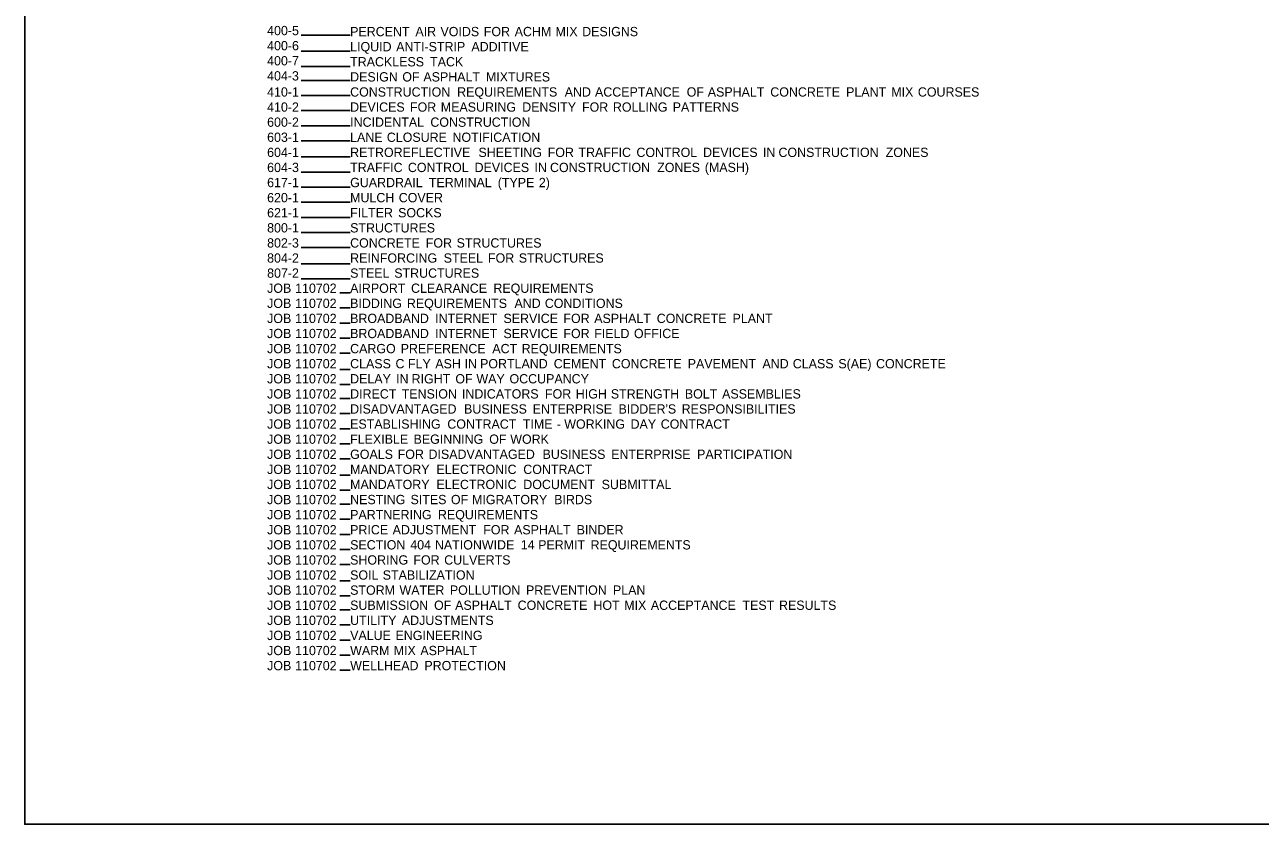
# Model space of a CAD drawing. Extents: x 1955683 to 1956002, y 566394 to 566602.
# Drawn here: x 1955683.4 to 1955842.9, y 566393.5 to 566496.8 of the extents above; entities that cross this region are included whole.
import ezdxf

# ---------------------------------------------------------------- set-up
doc = ezdxf.new("R2010")
doc.units = 0
doc.layers.add('Default', color=7, linetype='Continuous')
doc.layers.add('R_Border Prem', color=7, linetype='Continuous')

msp = doc.modelspace()

# ---------------------------------------------------------------- linework, layer by layer
at = {"layer": 'Default'}
for p, q in [((1955719.09, 566495.45), (1955725.4, 566495.45)), ((1955719.09, 566493.36), (1955725.4, 566493.36)), ((1955719.09, 566491.41), (1955725.4, 566491.41)), ((1955719.09, 566489.6), (1955725.4, 566489.6)), ((1955719.09, 566487.65), (1955725.4, 566487.65)), ((1955719.09, 566485.7), (1955725.4, 566485.7)), ((1955719.09, 566483.75), (1955725.4, 566483.75)), ((1955719.09, 566481.8), (1955725.4, 566481.8)), ((1955719.09, 566479.71), (1955725.4, 566479.71)), ((1955719.09, 566477.76), (1955725.4, 566477.76)), ((1955719.09, 566475.81), (1955725.4, 566475.81)), ((1955719.09, 566473.86), (1955725.4, 566473.86)), ((1955719.09, 566471.91), (1955725.4, 566471.91)), ((1955719.09, 566469.96), (1955725.4, 566469.96)), ((1955719.09, 566468.01), (1955725.4, 566468.01)), ((1955719.09, 566465.92), (1955725.4, 566465.92)), ((1955719.09, 566463.97), (1955725.4, 566463.97)), ((1955724.06, 566462.16), (1955725.4, 566462.16)), ((1955724.06, 566460.21), (1955725.4, 566460.21)), ((1955724.06, 566458.26), (1955725.4, 566458.26)), ((1955724.06, 566456.31), (1955725.4, 566456.31)), ((1955724.06, 566454.36), (1955725.4, 566454.36)), ((1955724.06, 566452.27), (1955725.4, 566452.27)), ((1955724.06, 566450.32), (1955725.4, 566450.32)), ((1955724.06, 566448.51), (1955725.4, 566448.51)), ((1955724.06, 566446.56), (1955725.4, 566446.56)), ((1955724.06, 566444.61), (1955725.4, 566444.61)), ((1955724.06, 566442.66), (1955725.4, 566442.66)), ((1955724.06, 566440.71), (1955725.4, 566440.71)), ((1955724.06, 566438.62), (1955725.4, 566438.62)), ((1955724.06, 566436.67), (1955725.4, 566436.67)), ((1955724.06, 566434.86), (1955725.4, 566434.86)), ((1955724.06, 566432.91), (1955725.4, 566432.91)), ((1955724.06, 566430.96), (1955725.4, 566430.96)), ((1955724.06, 566429.01), (1955725.4, 566429.01)), ((1955724.06, 566427.06), (1955725.4, 566427.06)), ((1955724.06, 566424.97), (1955725.4, 566424.97)), ((1955724.06, 566423.02), (1955725.4, 566423.02)), ((1955724.06, 566421.21), (1955725.4, 566421.21)), ((1955724.06, 566419.26), (1955725.4, 566419.26)), ((1955724.06, 566417.31), (1955725.4, 566417.31)), ((1955724.06, 566415.36), (1955725.4, 566415.36)), ((1955724.06, 566413.41), (1955725.4, 566413.41))]:
    msp.add_line(p, q, dxfattribs=at)
at = {"layer": 'R_Border Prem'}
msp.add_lwpolyline([(1956002.45, 566561.79), (1956002.45, 566393.51), (1955683.38, 566393.51), (1955683.38, 566601.97), (1955920.19, 566601.97), (1955920.19, 566592.09), (1955955.71, 566592.09), (1955955.71, 566588.52), (1955959.35, 566588.52), (1955959.35, 566589.17), (1955974.89, 566589.17)], dxfattribs=at)

# ---------------------------------------------------------------- texts
at = {"layer": 'Default'}
for s, p in [('400-5', (1955714.68, 566495.44)), ('PERCENT', (1955725.4, 566495.31)), (' AIR', (1955733.38, 566495.31)), (' VOIDS', (1955736.62, 566495.31)), (' FOR', (1955742.21, 566495.31)), (' ACHM', (1955746.2, 566495.31)), (' MIX', (1955751.47, 566495.31)), (' DESIGNS', (1955754.91, 566495.31)), ('400-6', (1955714.68, 566493.49)), ('LIQUID', (1955725.4, 566493.36)), (' ANTI-STRIP', (1955730.9, 566493.36)), (' ADDITIVE', (1955740.61, 566493.36)), ('400-7', (1955714.68, 566491.54)), ('TRACKLESS', (1955725.4, 566491.41)), (' TACK', (1955735.28, 566491.41)), ('404-3', (1955714.68, 566489.59)), ('DESIGN', (1955725.4, 566489.46)), (' OF', (1955731.69, 566489.46)), (' ASPHALT', (1955734.41, 566489.46)), (' MIXTURES', (1955742.48, 566489.46)), ('410-1', (1955714.68, 566487.51)), ('CONSTRUCTION', (1955725.4, 566487.51)), (' REQUIREMENTS', (1955738.77, 566487.51)), (' AND', (1955752.66, 566487.51)), (' ACCEPTANCE', (1955756.57, 566487.51)), (' OF', (1955768.41, 566487.51)), (' ASPHALT', (1955771.13, 566487.51)), (' CONCRETE', (1955779.2, 566487.51)), (' PLANT', (1955788.99, 566487.51)), (' MIX', (1955794.82, 566487.51)), (' COURSES', (1955798.26, 566487.51)), ('410-2', (1955714.68, 566485.56)), ('DEVICES', (1955725.4, 566485.56)), (' FOR', (1955732.68, 566485.56)), (' MEASURING', (1955736.66, 566485.56)), (' DENSITY', (1955747.17, 566485.56)), (' FOR', (1955754.89, 566485.56)), (' ROLLING', (1955758.88, 566485.56)), (' PATTERNS', (1955766.6, 566485.56)), ('600-2', (1955714.68, 566483.61)), ('INCIDENTAL', (1955725.4, 566483.61)), (' CONSTRUCTION', (1955735.31, 566483.61)), ('603-1', (1955714.68, 566481.66)), ('LANE', (1955725.4, 566481.66)), (' CLOSURE', (1955729.69, 566481.66)), (' NOTIFICATION', (1955738.17, 566481.66)), ('604-1', (1955714.68, 566479.71)), ('RETROREFLECTIVE', (1955725.4, 566479.71)), (' SHEETING', (1955741.52, 566479.71)), (' FOR', (1955750.46, 566479.71)), (' TRAFFIC', (1955754.44, 566479.71)), (' CONTROL', (1955761.92, 566479.71)), (' DEVICES', (1955770.52, 566479.71)), (' IN', (1955778.26, 566479.71)), (' CONSTRUCTION', (1955780.26, 566479.71)), (' ZONES', (1955794.1, 566479.71)), ('604-3', (1955714.68, 566477.76)), ('TRAFFIC', (1955725.4, 566477.76)), (' CONTROL', (1955732.41, 566477.76)), (' DEVICES', (1955741.02, 566477.76)), (' IN', (1955748.76, 566477.76)), (' CONSTRUCTION', (1955750.76, 566477.76)), (' ZONES', (1955764.6, 566477.76)), (' (MASH)', (1955770.75, 566477.76)), ('617-1', (1955714.68, 566475.81)), ('GUARDRAIL', (1955725.4, 566475.81)), (' TERMINAL', (1955735.12, 566475.81)), (' (TYPE', (1955744.01, 566475.81)), (' 2)', (1955749.32, 566475.81)), ('620-1', (1955714.68, 566473.86)), ('MULCH', (1955725.4, 566473.86)), (' COVER', (1955731.23, 566473.86)), ('621-1', (1955714.68, 566471.91)), ('FILTER', (1955725.4, 566471.91)), (' SOCKS', (1955731.15, 566471.91)), ('800-1', (1955714.68, 566469.96)), ('STRUCTURES', (1955725.4, 566469.96)), ('802-3', (1955714.68, 566468.01)), ('CONCRETE', (1955725.4, 566468.01)), (' FOR', (1955734.72, 566468.01)), (' STRUCTURES', (1955738.7, 566468.01)), ('804-2', (1955714.68, 566466.06)), ('REINFORCING', (1955725.4, 566466.06)), (' STEEL', (1955737.03, 566466.06)), (' FOR', (1955742.75, 566466.06)), (' STRUCTURES', (1955746.73, 566466.06)), ('807-2', (1955714.68, 566464.11)), ('STEEL', (1955725.4, 566464.11)), (' STRUCTURES', (1955730.65, 566464.11)), ('JOB', (1955714.68, 566462.16)), (' 110702', (1955717.85, 566462.16)), ('AIRPORT', (1955725.4, 566462.16)), (' CLEARANCE', (1955732.82, 566462.16)), (' REQUIREMENTS', (1955743.45, 566462.16)), ('JOB', (1955714.68, 566460.21)), (' 110702', (1955717.85, 566460.21)), ('BIDDING', (1955725.4, 566460.21)), (' REQUIREMENTS', (1955732.28, 566460.21)), (' AND', (1955746.17, 566460.21)), (' CONDITIONS', (1955750.09, 566460.21)), ('JOB', (1955714.68, 566458.26)), (' 110702', (1955717.85, 566458.26)), ('BROADBAND', (1955725.4, 566458.26)), (' INTERNET', (1955735.93, 566458.26)), (' SERVICE', (1955744.75, 566458.26)), (' FOR', (1955752.49, 566458.26)), (' ASPHALT', (1955756.47, 566458.26)), (' CONCRETE', (1955764.54, 566458.26)), (' PLANT', (1955774.33, 566458.26)), ('JOB', (1955714.68, 566456.31)), (' 110702', (1955717.85, 566456.31)), ('BROADBAND', (1955725.4, 566456.31)), (' INTERNET', (1955735.93, 566456.31)), (' SERVICE', (1955744.75, 566456.31)), (' FOR', (1955752.49, 566456.31)), (' FIELD', (1955756.47, 566456.31)), (' OFFICE', (1955761.6, 566456.31)), ('JOB', (1955714.68, 566454.36)), (' 110702', (1955717.85, 566454.36)), ('CARGO', (1955725.4, 566454.36)), (' PREFERENCE', (1955731.48, 566454.36)), (' ACT', (1955743.31, 566454.36)), (' REQUIREMENTS', (1955747.1, 566454.36)), ('JOB', (1955714.68, 566452.41)), (' 110702', (1955717.85, 566452.41)), ('CLASS', (1955725.4, 566452.41)), (' C', (1955730.81, 566452.41)), (' FLY', (1955732.42, 566452.41)), (' ASH', (1955735.95, 566452.41)), (' IN', (1955739.73, 566452.41)), (' PORTLAND', (1955741.73, 566452.41)), (' CEMENT', (1955751.24, 566452.41)), (' CONCRETE', (1955758.75, 566452.41)), (' PAVEMENT', (1955768.54, 566452.41)), (' AND', (1955778.19, 566452.41)), (' CLASS', (1955782.11, 566452.41)), (' S(AE)', (1955787.99, 566452.41)), (' CONCRETE', (1955792.86, 566452.41)), ('JOB', (1955714.68, 566450.46)), (' 110702', (1955717.85, 566450.46)), ('DELAY', (1955725.4, 566450.46)), (' IN', (1955730.89, 566450.46)), (' RIGHT', (1955732.89, 566450.46)), (' OF', (1955738.54, 566450.46)), (' WAY', (1955741.26, 566450.46)), (' OCCUPANCY', (1955745.53, 566450.46)), ('JOB', (1955714.68, 566448.51)), (' 110702', (1955717.85, 566448.51)), ('DIRECT', (1955725.4, 566448.51)), (' TENSION', (1955731.61, 566448.51)), (' INDICATORS', (1955739.39, 566448.51)), (' FOR', (1955750.11, 566448.51)), (' HIGH', (1955754.09, 566448.51)), (' STRENGTH', (1955758.61, 566448.51)), (' BOLT', (1955768.17, 566448.51)), (' ASSEMBLIES', (1955772.98, 566448.51)), ('JOB', (1955714.68, 566446.56)), (' 110702', (1955717.85, 566446.56)), ('DISADVANTAGED', (1955725.4, 566446.56)), (' BUSINESS', (1955739.66, 566446.56)), (' ENTERPRISE', (1955748.52, 566446.56)), (" BIDDER'S", (1955759.61, 566446.56)), (' RESPONSIBILITIES', (1955767.76, 566446.56)), ('JOB', (1955714.68, 566444.61)), (' 110702', (1955717.85, 566444.61)), ('ESTABLISHING', (1955725.4, 566444.61)), (' CONTRACT', (1955737.5, 566444.61)), (' TIME', (1955747.25, 566444.61)), (' WORKING', (1955752.6, 566444.61)), (' DAY', (1955761.16, 566444.61)), (' CONTRACT', (1955765.06, 566444.61)), (' -', (1955751.63, 566444.61)), ('JOB', (1955714.68, 566442.66)), (' 110702', (1955717.85, 566442.66)), ('FLEXIBLE', (1955725.4, 566442.66)), (' BEGINNING', (1955733.14, 566442.66)), (' OF', (1955742.91, 566442.66)), (' WORK', (1955745.63, 566442.66)), ('JOB', (1955714.68, 566440.71)), (' 110702', (1955717.85, 566440.71)), ('GOALS', (1955725.4, 566440.71)), (' FOR', (1955731.09, 566440.71)), (' DISADVANTAGED', (1955735.07, 566440.71)), (' BUSINESS', (1955749.8, 566440.71)), (' ENTERPRISE', (1955758.66, 566440.71)), (' PARTICIPATION', (1955769.75, 566440.71)), ('JOB', (1955714.68, 566438.76)), (' 110702', (1955717.85, 566438.76)), ('MANDATORY', (1955725.4, 566438.76)), (' ELECTRONIC', (1955736.1, 566438.76)), (' CONTRACT', (1955747.31, 566438.76)), ('JOB', (1955714.68, 566436.81)), (' 110702', (1955717.85, 566436.81)), ('MANDATORY', (1955725.4, 566436.81)), (' ELECTRONIC', (1955736.1, 566436.81)), (' DOCUMENT', (1955747.31, 566436.81)), (' SUBMITTAL', (1955757.43, 566436.81)), ('JOB', (1955714.68, 566434.86)), (' 110702', (1955717.85, 566434.86)), ('NESTING', (1955725.4, 566434.86)), (' SITES', (1955732.75, 566434.86)), (' OF', (1955737.97, 566434.86)), (' MIGRATORY', (1955740.69, 566434.86)), (' BIRDS', (1955751.3, 566434.86)), ('JOB', (1955714.68, 566432.91)), (' 110702', (1955717.85, 566432.91)), ('PARTNERING', (1955725.4, 566432.91)), (' REQUIREMENTS', (1955736.29, 566432.91)), ('JOB', (1955714.68, 566430.96)), (' 110702', (1955717.85, 566430.96)), ('PRICE', (1955725.4, 566430.96)), (' ADJUSTMENT', (1955730.44, 566430.96)), (' FOR', (1955742.14, 566430.96)), (' ASPHALT', (1955746.12, 566430.96)), (' BINDER', (1955754.2, 566430.96)), ('JOB', (1955714.68, 566429.01)), (' 110702', (1955717.85, 566429.01)), ('SECTION', (1955725.4, 566429.01)), (' 404', (1955732.72, 566429.01)), (' NATIONWIDE', (1955735.9, 566429.01)), (' 14', (1955746.99, 566429.01)), (' PERMIT', (1955749.23, 566429.01)), (' REQUIREMENTS', (1955756, 566429.01)), ('JOB', (1955714.68, 566427.06)), (' 110702', (1955717.85, 566427.06)), ('SHORING', (1955725.4, 566427.06)), (' FOR', (1955733.12, 566427.06)), (' CULVERTS', (1955737.1, 566427.06)), ('JOB', (1955714.68, 566425.11)), (' 110702', (1955717.85, 566425.11)), ('SOIL', (1955725.4, 566425.11)), (' STABILIZATION', (1955729.16, 566425.11)), ('JOB', (1955714.68, 566423.16)), (' 110702', (1955717.85, 566423.16)), ('STORM', (1955725.4, 566423.16)), (' WATER', (1955731.33, 566423.16)), (' POLLUTION', (1955737.83, 566423.16)), (' PREVENTION', (1955747.66, 566423.16)), (' PLAN', (1955758.89, 566423.16)), ('JOB', (1955714.68, 566421.21)), (' 110702', (1955717.85, 566421.21)), ('SUBMISSION', (1955725.4, 566421.21)), (' OF', (1955735.79, 566421.21)), (' ASPHALT', (1955738.51, 566421.21)), (' CONCRETE', (1955746.58, 566421.21)), (' HOT', (1955756.37, 566421.21)), (' MIX', (1955760.34, 566421.21)), (' ACCEPTANCE', (1955763.78, 566421.21)), (' TEST', (1955775.61, 566421.21)), (' RESULTS', (1955780.33, 566421.21)), ('JOB', (1955714.68, 566419.26)), (' 110702', (1955717.85, 566419.26)), ('UTILITY', (1955725.4, 566419.26)), (' ADJUSTMENTS', (1955731.63, 566419.26)), ('JOB', (1955714.68, 566417.31)), (' 110702', (1955717.85, 566417.31)), ('VALUE', (1955725.4, 566417.31)), (' ENGINEERING', (1955730.81, 566417.31)), ('JOB', (1955714.68, 566415.36)), (' 110702', (1955717.85, 566415.36)), ('WARM', (1955725.4, 566415.36)), (' MIX', (1955730.58, 566415.36)), (' ASPHALT', (1955734.02, 566415.36)), ('JOB', (1955714.68, 566413.41)), (' 110702', (1955717.85, 566413.41)), ('WELLHEAD', (1955725.4, 566413.41)), (' PROTECTION', (1955734.54, 566413.41))]:
    msp.add_text(s, height=1.2, dxfattribs=at).set_placement(p)

doc.saveas('drawing.dxf')
